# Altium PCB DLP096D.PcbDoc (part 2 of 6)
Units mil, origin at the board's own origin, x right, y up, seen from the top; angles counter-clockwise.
Board outline 4950 x 3159.45 mil, 8 copper layers (Top Layer, GND1, SIGNAL1, POWER1, POWER2, SIGNAL2, GND2, Bottom Layer), stack 60.4 mil thick; 328 components, 223 nets, 1380 pads, 856 vias.
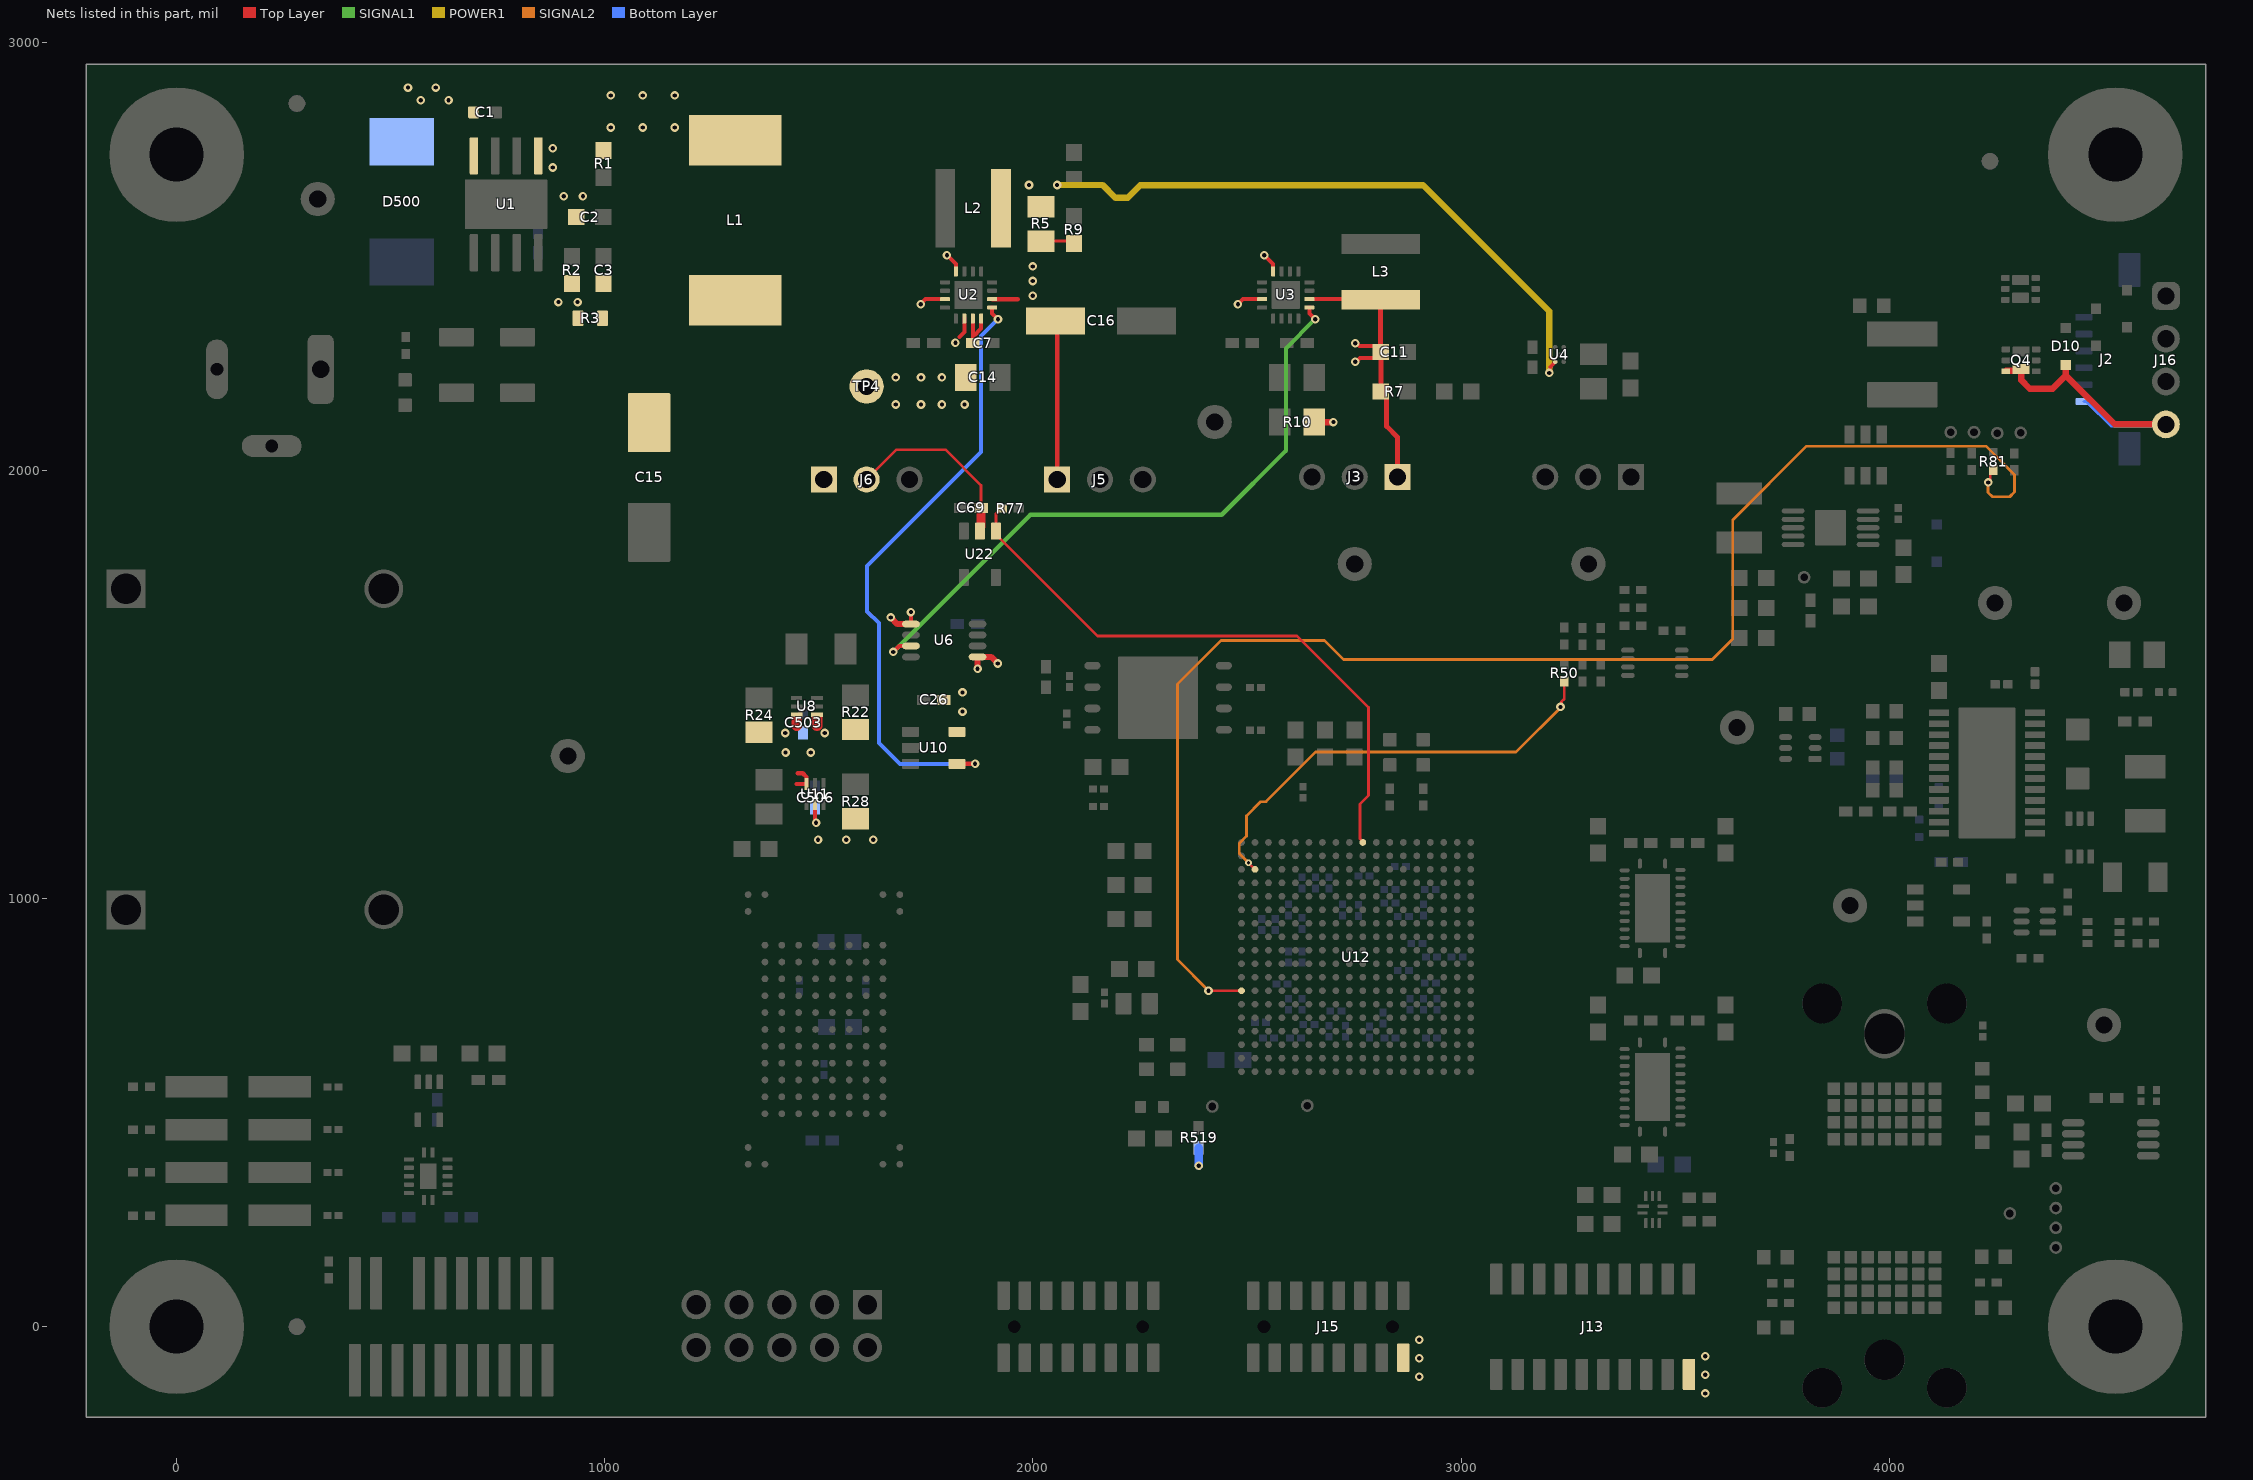
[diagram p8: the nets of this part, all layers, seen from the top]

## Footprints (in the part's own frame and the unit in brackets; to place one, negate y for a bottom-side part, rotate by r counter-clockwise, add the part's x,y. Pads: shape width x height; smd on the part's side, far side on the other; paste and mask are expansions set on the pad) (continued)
PWP0024B_NV_L [mm] "TSOP, 24-Leads, Body 7.9x4.5mm (max), Pitch 0.65mm, IPC High Density"
  rrect25% 1.2x0.4 smd: 1(-2.85,3.575) 2(-2.85,2.925) 3(-2.85,2.275) 4(-2.85,1.625) 5(-2.85,0.975) 6(-2.85,0.325) 7(-2.85,-0.325) 8(-2.85,-0.975) 9(-2.85,-1.625) 10(-2.85,-2.275) 11(-2.85,-2.925) 12(-2.85,-3.575) 13(2.85,-3.575) 14(2.85,-2.925) 15(2.85,-2.275) 16(2.85,-1.625) 17(2.85,-0.975) 18(2.85,-0.325) 19(2.85,0.325) 20(2.85,0.975) 21(2.85,1.625) 22(2.85,2.275) 23(2.85,2.925) 24(2.85,3.575)
  rrect6% 3.4x7.8 smd paste-2 mask-2: 25(0,0)
  rrect4% 2.4x5.16 on Top Paste: 25(0,0)
  rrect4% 2.4x5.16 on Top Solder: 25(0,0)
  silkscreen extent -2,-3.95 1.7,3.95, body extent -3.21,-3.9 3.21,3.9, height 1.2
RGT0016C [mm] "QFN, 16-Leads, Body 3x3mm, Pitch 0.5mm, Thermal Pad 1.7x1.7mm, TI Recommended"
  rrect42% 0.6x0.24 smd: 1(-1.4,0.75) 2(-1.4,0.25) 3(-1.4,-0.25) 4(-1.4,-0.75) 9(1.4,-0.75) 10(1.4,-0.25) 11(1.4,0.25) 12(1.4,0.75)
  rrect42% 0.24x0.6 smd: 5(-0.75,-1.4) 6(-0.25,-1.4) 7(0.25,-1.4) 8(0.75,-1.4) 13(0.75,1.4) 14(0.25,1.4) 15(-0.25,1.4) 16(-0.75,1.4)
  rrect6% 1.55x1.55 on Top Paste: 17(0,0)
  rrect6% 1.68x1.68 smd paste-0.85: 17(0,0)
  silkscreen extent -1.72,-1.73 1.73,1.73, body extent -1.5,-1.5 1.5,1.5, height 1
RHL0024A [mm]
  oval 0.24x0.6 smd: 1(-0.75,2.65) 12(-0.75,-2.65) 13(0.75,-2.65) 24(0.75,2.65)
  oval 0.6x0.24 smd: 2(-1.65,2.25) 3(-1.65,1.75) 4(-1.65,1.25) 5(-1.65,0.75) 6(-1.65,0.25) 7(-1.65,-0.25) 8(-1.65,-0.75) 9(-1.65,-1.25) 10(-1.65,-1.75) 11(-1.65,-2.25) 14(1.65,-2.225) 15(1.65,-1.725) 16(1.65,-1.225) 17(1.65,-0.725) 18(1.65,-0.225) 19(1.65,0.275) 20(1.65,0.775) 21(1.65,1.275) 22(1.65,1.775) 23(1.65,2.275)
  rect 2.05x4.05 smd paste-1.1: 25(0,0)
  Top Layer region: 0.396,-2 0.154,-2 0.154,-2.75 0.396,-2.75
  Top Layer region: -0.152,-2 -0.394,-2 -0.394,-2.75 -0.152,-2.75
  Top Layer region: -0.395,2.024 0.395,2.024 0.395,2.225 -0.395,2.225
  Top Layer region: 0.152,2 0.394,2 0.394,2.75 0.152,2.75
  Top Layer region: -0.396,2 -0.154,2 -0.154,2.75 -0.396,2.75
  Top Layer region: -0.395,-2.225 0.395,-2.225 0.395,-2.024 -0.395,-2.024
  silkscreen extent -1.95,-2.95 1.95,2.95, body extent -1.82,-2.82 1.82,2.82, height 1.01
RSW0010A [mm] "QFN, 10-Leads, Body 1.8x1.4 mm, Pitch 0.4mm, TI Recommended"
  rrect50% 0.7x0.2 smd: 1(-0.55,0.2)
  rrect50% 0.6x0.2 smd: 2(-0.6,-0.2) 6(0.6,-0.2) 7(0.6,0.2)
  rrect50% 0.2x0.6 smd: 3(-0.4,-0.8) 4(0,-0.8) 5(0.4,-0.8) 8(0.4,0.8) 9(0,0.8) 10(-0.4,0.8)
  silkscreen extent -0.88,-1.08 0.88,1.08, body extent -0.7,-0.9 0.7,0.9, height 0.56
Samtec_FLE-108-01-x-DV-A [mm] "Receptacle, 1.27mm, 8x2, SMT"
  rrect14% 0.74x1.675 smd: 1(-4.445,1.843) 2(-4.445,-1.842) 3(-3.175,1.843) 4(-3.175,-1.842) 5(-1.905,1.843) 6(-1.905,-1.842) 7(-0.635,1.843) 8(-0.635,-1.842) 9(0.635,1.843) 10(0.635,-1.842) 11(1.905,1.843) 12(1.905,-1.842) 13(3.175,1.843) 14(3.175,-1.842) 15(4.445,1.843) 16(4.445,-1.842)
  round 0.46 hole 0.76 unplated: ""(-3.81,0) ""(3.81,0)
  silkscreen extent -5.5,-1.5 5.2,1.5, body extent -5.14,-2.3 5.14,2.3, height 4.55
Samtec_RSM-110-02-x-D [mm] "Receptacle, 1.27mm, 10x2, SMT"
  rrect14% 0.74x1.84 smd: 1(-5.715,2.825) 2(-5.715,-2.825) 3(-4.445,2.825) 4(-4.445,-2.825) 5(-3.175,2.825) 6(-3.175,-2.825) 7(-1.905,2.825) 8(-1.905,-2.825) 9(-0.635,2.825) 10(-0.635,-2.825) 11(0.635,2.825) 12(0.635,-2.825) 13(1.905,2.825) 14(1.905,-2.825) 15(3.175,2.825) 16(3.175,-2.825) 17(4.445,2.825) 18(4.445,-2.825) 19(5.715,2.825) 20(5.715,-2.825)
  body extent -6.48,-3.24 6.48,3.24, height 6.1
Samtec_TSM-104-01-x-DV [mm] "Header, 2.54mm, 4x2, SMT"
  rect 3.68x1.27 smd: 1(-2.475,3.81) 2(2.475,3.81) 3(-2.475,1.27) 4(2.475,1.27) 5(-2.475,-1.27) 6(2.475,-1.27) 7(-2.475,-3.81) 8(2.475,-3.81)
  silkscreen extent -1.65,-5.08 1.65,5.22, body extent -3.85,-5.08 3.85,5.08, height 9.65
SM_RADIAL_6.3BMM [mm] "Nichicon 6.3x7.7"
  rect 3.5x1.6 smd: 1(-2.7,0) 2(2.7,0)
  silkscreen extent -3.4,-3.4 3.4,3.4, body extent -3.4,-3.4 3.4,3.4, height 8
SMC [mil] "Molded Diode, 2-Leads, Body 6.9x5.8mm, IPC Medium Density, based on OnSemi component dimensions and land patterns"
  rect 110x150 smd: 1(-140.49,0) 2(140.49,0)
  silkscreen extent -221,-123 189,124, body extent -156,-116 156,116, height 91
SOD-323#1 [mm] "NXP recommended land pattern"
  rect 0.6x0.6 smd paste-0.05: 1(-1.1,0) 2(1.1,0)
  silkscreen extent -2.06,-0.86 1.53,0.86, body extent -1.3,-0.67 1.3,0.68, height 1.1
SOD-323#2 [mm] "NXP recommended land pattern"
  rect 0.6x0.6 smd: 1(-1.1,0) 2(1.1,0)
  silkscreen extent -2.06,-0.86 1.53,0.86, body extent -1.3,-0.67 1.3,0.68, height 1.1
SOT-26 [mm] "SOT23, 6-Leads, Body 3.1x3.0mm (max), Pitch 0.95mm, IPC Medium Density based on Diodes Inc ap02002.pdf rev 29"
  rect 1.05x0.6 smd: 1(-1.225,0.95) 2(-1.225,0) 3(-1.225,-0.95) 4(1.225,-0.95) 5(1.225,0) 6(1.225,0.95)
  silkscreen extent -0.3,-1.55 0.3,1.55, body extent -1.5,-1.5 1.5,1.5, height 1.3
SOT-363 [mm]
  rect 0.6x0.42 smd: 1(-0.95,0.65) 2(-0.95,0) 3(-0.95,-0.65) 4(0.95,-0.65) 5(0.95,0) 6(0.95,0.65)
  silkscreen extent -0.38,-1.02 0.38,1.02, body extent -1.1,-1.1 1.1,1.1, height 1.12
SRN5040TA [mm] "Bourns"
  rrect7% 1.5x4.2 smd: 1(-1.8,0) 2(1.8,0)
  body extent -2.42,-2.43 2.43,2.42, height 3.81
TI_Stacked_Overlay_Small [mil]
  silkscreen extent -418,-98 418,98
TP_H045P075 [mm] "TP_H0.45P0.75"
  round 0.75 hole 0.45: 1(0,0)
TSW-104-07-G-S [mm] "Samtec 100mil, 1x4, 230 mil above insulator"
  rrect50% 1.65x1.65 hole 1.016: 1(-3.81,0)
  round 1.65 hole 1.016: 2(-1.27,0) 3(1.27,0) 4(3.81,0)
  body extent -5.08,-1.27 5.08,1.27, height 8.38
U-DFN2020-6_B [mm] "SMD, 6-Leads, Body 2x2mm, Pitch 0.65mm"
  rrect29% 0.5x0.35 smd: 1(-0.9,0.65) 2(-0.9,0) 3(-0.9,-0.65) 4(0.9,-0.65) 5(0.9,0) 6(0.9,0.65)
  rrect17% 1x0.6 smd: 7(0,0.525) 8(0,-0.525)
  silkscreen extent -1.04,-1.19 1.04,1.4, body extent -1.04,-1.04 1.04,1.04, height 0.58
WEEE_Minimum [mil] "WEEElie bin"
  silkscreen extent -95,-172 99,104
XAL5030 [mil] "Coilcraft XAL5030 12/12/11"
  rect 46x183 smd: 1(-65,0) 2(65,0)
  silkscreen extent -108,-112 108,112, body extent -108,-112 108,112, height 122
YZR0005AEBA [mm] "Micro SMD, 5-Leads, Body 1.39x1.06mm, Pitch 0.5mm, NSC Recommended"
  round 0.265 smd paste-0.132 mask+0.05: A1(-0.25,0.433) A3(0.25,0.433) B2(0,0) C1(-0.25,-0.433) C3(0.25,-0.433)
  silkscreen extent -0.68,0.75 -0.58,0.85, body extent -0.53,-0.7 0.53,0.69, height 0.68
ZCZ0324A-MFG [mm]
  round 0.4 smd paste+0 mask+0: A1(-6.8,6.8) A2(-6,6.8) A3(-5.2,6.8) A4(-4.4,6.8) A5(-3.6,6.8) A6(-2.8,6.8) A7(-2,6.8) A8(-1.2,6.8) A9(-0.4,6.8) A10(0.4,6.8) A11(1.2,6.8) A12(2,6.8) A13(2.8,6.8) A14(3.6,6.8) A15(4.4,6.8) A16(5.2,6.8) A17(6,6.8) A18(6.8,6.8) B1(-6.8,6) B2(-6,6) B3(-5.2,6) B4(-4.4,6) B5(-3.6,6) B6(-2.8,6) B7(-2,6) B8(-1.2,6) B9(-0.4,6) B10(0.4,6) B11(1.2,6) B12(2,6) B13(2.8,6) B14(3.6,6) B15(4.4,6) B16(5.2,6) B17(6,6) B18(6.8,6) C1(-6.8,5.2) C2(-6,5.2) C3(-5.2,5.2) C4(-4.4,5.2) C5(-3.6,5.2) C6(-2.8,5.2) C7(-2,5.2) C8(-1.2,5.2) C9(-0.4,5.2) C10(0.4,5.2) C11(1.2,5.2) C12(2,5.2) C13(2.8,5.2) C14(3.6,5.2) C15(4.4,5.2) C16(5.2,5.2) C17(6,5.2) C18(6.8,5.2) D1(-6.8,4.4) D2(-6,4.4) D3(-5.2,4.4) D4(-4.4,4.4) D5(-3.6,4.4) D6(-2.8,4.4) D7(-2,4.4) D8(-1.2,4.4) D9(-0.4,4.4) D10(0.4,4.4) D11(1.2,4.4) D12(2,4.4) D13(2.8,4.4) D14(3.6,4.4) D15(4.4,4.4) D16(5.2,4.4) D17(6,4.4) D18(6.8,4.4) E1(-6.8,3.6) E2(-6,3.6) E3(-5.2,3.6) E4(-4.4,3.6) E5(-3.6,3.6) E6(-2.8,3.6) E7(-2,3.6) E8(-1.2,3.6) E9(-0.4,3.6) E10(0.4,3.6) E11(1.2,3.6) E12(2,3.6) E13(2.8,3.6) E14(3.6,3.6) E15(4.4,3.6) E16(5.2,3.6) E17(6,3.6) E18(6.8,3.6) F1(-6.8,2.8) F2(-6,2.8) F3(-5.2,2.8) F4(-4.4,2.8) F5(-3.6,2.8) F6(-2.8,2.8) F7(-2,2.8) F8(-1.2,2.8) F9(-0.4,2.8) F10(0.4,2.8) F11(1.2,2.8) F12(2,2.8) F13(2.8,2.8) F14(3.6,2.8) F15(4.4,2.8) F16(5.2,2.8) F17(6,2.8) F18(6.8,2.8) G1(-6.8,2) G2(-6,2) G3(-5.2,2) G4(-4.4,2) G5(-3.6,2) G6(-2.8,2) G7(-2,2) G8(-1.2,2) G9(-0.4,2) G10(0.4,2) G11(1.2,2) G12(2,2) G13(2.8,2) G14(3.6,2) G15(4.4,2) G16(5.2,2) G17(6,2) G18(6.8,2) H1(-6.8,1.2) H2(-6,1.2) H3(-5.2,1.2) H4(-4.4,1.2) H5(-3.6,1.2) H6(-2.8,1.2) H7(-2,1.2) H8(-1.2,1.2) H9(-0.4,1.2) H10(0.4,1.2) H11(1.2,1.2) H12(2,1.2) H13(2.8,1.2) H14(3.6,1.2) H15(4.4,1.2) H16(5.2,1.2) H17(6,1.2) H18(6.8,1.2) J1(-6.8,0.4) J2(-6,0.4) J3(-5.2,0.4) J4(-4.4,0.4) J5(-3.6,0.4) J6(-2.8,0.4) J7(-2,0.4) J8(-1.2,0.4) J9(-0.4,0.4) J10(0.4,0.4) J11(1.2,0.4) J12(2,0.4) J13(2.8,0.4) J14(3.6,0.4) J15(4.4,0.4) J16(5.2,0.4) J17(6,0.4) J18(6.8,0.4) K1(-6.8,-0.4) K2(-6,-0.4) K3(-5.2,-0.4) K4(-4.4,-0.4) K5(-3.6,-0.4) K6(-2.8,-0.4) K7(-2,-0.4) K8(-1.2,-0.4) K9(-0.4,-0.4) K10(0.4,-0.4) K11(1.2,-0.4) K12(2,-0.4) K13(2.8,-0.4) K14(3.6,-0.4) K15(4.4,-0.4) K16(5.2,-0.4) K17(6,-0.4) K18(6.8,-0.4) L1(-6.8,-1.2) L2(-6,-1.2) L3(-5.2,-1.2) L4(-4.4,-1.2) L5(-3.6,-1.2) L6(-2.8,-1.2) L7(-2,-1.2) L8(-1.2,-1.2) L9(-0.4,-1.2) L10(0.4,-1.2) L11(1.2,-1.2) L12(2,-1.2) L13(2.8,-1.2) L14(3.6,-1.2) L15(4.4,-1.2) L16(5.2,-1.2) L17(6,-1.2) L18(6.8,-1.2) M1(-6.8,-2) M2(-6,-2) M3(-5.2,-2) M4(-4.4,-2) M5(-3.6,-2) M6(-2.8,-2) M7(-2,-2) M8(-1.2,-2) M9(-0.4,-2) M10(0.4,-2) M11(1.2,-2) M12(2,-2) M13(2.8,-2) M14(3.6,-2) M15(4.4,-2) M16(5.2,-2) M17(6,-2) M18(6.8,-2) N1(-6.8,-2.8) N2(-6,-2.8) N3(-5.2,-2.8) N4(-4.4,-2.8) N5(-3.6,-2.8) N6(-2.8,-2.8) N7(-2,-2.8) N8(-1.2,-2.8) N9(-0.4,-2.8) N10(0.4,-2.8) N11(1.2,-2.8) N12(2,-2.8) N13(2.8,-2.8) N14(3.6,-2.8) N15(4.4,-2.8) N16(5.2,-2.8) N17(6,-2.8) N18(6.8,-2.8) P1(-6.8,-3.6) P2(-6,-3.6) P3(-5.2,-3.6) P4(-4.4,-3.6) P5(-3.6,-3.6) P6(-2.8,-3.6) P7(-2,-3.6) P8(-1.2,-3.6) P9(-0.4,-3.6) P10(0.4,-3.6) P11(1.2,-3.6) P12(2,-3.6) P13(2.8,-3.6) P14(3.6,-3.6) P15(4.4,-3.6) P16(5.2,-3.6) P17(6,-3.6) P18(6.8,-3.6) R1(-6.8,-4.4) R2(-6,-4.4) R3(-5.2,-4.4) R4(-4.4,-4.4) R5(-3.6,-4.4) R6(-2.8,-4.4) R7(-2,-4.4) R8(-1.2,-4.4) R9(-0.4,-4.4) R10(0.4,-4.4) R11(1.2,-4.4) R12(2,-4.4) R13(2.8,-4.4) R14(3.6,-4.4) R15(4.4,-4.4) R16(5.2,-4.4) R17(6,-4.4) R18(6.8,-4.4) T1(-6.8,-5.2) T2(-6,-5.2) T3(-5.2,-5.2) T4(-4.4,-5.2) T5(-3.6,-5.2) T6(-2.8,-5.2) T7(-2,-5.2) T8(-1.2,-5.2) T9(-0.4,-5.2) T10(0.4,-5.2) T11(1.2,-5.2) T12(2,-5.2) T13(2.8,-5.2) T14(3.6,-5.2) T15(4.4,-5.2) T16(5.2,-5.2) T17(6,-5.2) T18(6.8,-5.2) U1(-6.8,-6) U2(-6,-6) U3(-5.2,-6) U4(-4.4,-6) U5(-3.6,-6) U6(-2.8,-6) U7(-2,-6) U8(-1.2,-6) U9(-0.4,-6) U10(0.4,-6) U11(1.2,-6) U12(2,-6) U13(2.8,-6) U14(3.6,-6) U15(4.4,-6) U16(5.2,-6) U17(6,-6) U18(6.8,-6) V1(-6.8,-6.8) V2(-6,-6.8) V3(-5.2,-6.8) V4(-4.4,-6.8) V5(-3.6,-6.8) V6(-2.8,-6.8) V7(-2,-6.8) V8(-1.2,-6.8) V9(-0.4,-6.8) V10(0.4,-6.8) V11(1.2,-6.8) V12(2,-6.8) V13(2.8,-6.8) V14(3.6,-6.8) V15(4.4,-6.8) V16(5.2,-6.8) V17(6,-6.8) V18(6.8,-6.8)
  silkscreen extent -8.15,-7.55 7.55,7.55, body extent -8.05,-8.05 8.05,8.05, height 0.25

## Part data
C1: library part CMP-0086535-1, "0.1µF ±10% 50V Ceramic Capacitor X8L 0603 (1608 Metric)", Manufacturer="Murata Electronics North America", TempCo=-40+15%, Tolerance_%=10%
C2: library part CMP-0006792-3, "CAP, CERM, 56 pF, 50 V, +/- 1%, C0G/NP0, 0603", Cap_Case=0603, Manufacturer=AVX, Supplier Part Number 1=478-7922-1-ND, TempCo=C0G/NP0, Tolerance_%=1%, Value1=Unknown, Value2=50V, ValueDisplayed=56pF
C3: library part CMP-0007180-1, "CAP, CERM, 1200 pF, 50 V, +/- 5%, C0G/NP0, 0603", Cap_Case=0603, Manufacturer=MuRata, Supplier Part Number 1=490-1453-1-ND, TempCo=C0G/NP0, Tolerance_%=5%, Value1=Unknown, Value2=50V, ValueDisplayed=1200pF
C4 C5: library part CMP-0089367-1, "2.2µF ±10% 100V Ceramic Capacitor X8L 1210 (3225 Metric)", Digikey Part Number=490-GCJ32DL8EL225KA07LCT-ND, Manufacturer=Murata, Mouser Part Number=81-GCJ32DL8EL225KA7L, Operating Temperature Range="-55°C to +150°C", TempCo=+15/-40%, Temperature Characteristic=X8L, Tolerance_%=10%, ValueDisplayed=2.2uF
C6: library part CMP-0080703-2, "CAP, CERM, 390 pF, 50 V,+/- 10%, X7R, AEC-Q200 Grade 1, 0402", Cap_Case=0402, Manufacturer=MuRata, Supplier Part Number 1=81-GCM155R71H391KA7D, TempCo=X7R, Tolerance_%=10%, Value2=50V, ValueDisplayed=390pF
C7 C9 C26 C65 C69 C501 C503 C506 C507 C555 C556 C557: library part CMP-0078241-1, "CAP, CERM, 0.1 µF, 10 V,+/- 10%, X7R, 0402", Cap_Case=0402, Manufacturer=Kemet, Supplier Part Number 1=399-3520-1-ND, TempCo=X7R, Tolerance_%=10%, Value2=10V, ValueDisplayed=0.1µF
C8: library part CMP-0006310-2, "CAP, CERM, 150 pF, 50 V, +/- 5%, C0G/NP0, AEC-Q200 Grade 1, 0402", Cap_Case=0402, Manufacturer=TDK, Supplier Part Number 1=445-5598-1-ND, TempCo=C0G/NP0, Tolerance_%=5%, Value1=Unknown, Value2=50V, ValueDisplayed=150pF
C10: library part CMP-0080385-1, "CAP, CERM, 4.7 µF,  VAC/6.3 VDC,+/- 20%, X5R, 0402", Cap_Case=0402, Manufacturer=MuRata, Supplier Part Number 1=GRM155R60J475ME47J-ND, TempCo=X5R, Tolerance_%=20%, Value1="0.001 ohm", Value2=6.3V, ValueDisplayed=4.7µF
C11 C12 C51: library part CMP-0078295-1, "CAP, CERM, 22 µF, 6.3 V,+/- 20%, X5R, 0603", Cap_Case=0603, Manufacturer=MuRata, Supplier Part Number 1=490-13241-1-ND, TempCo=X5R, Tolerance_%=20%, Value2=6.3V, ValueDisplayed=22µF
C13 C14: library part CMP-0085574-1, "CAP, CERM, 10 µF, 10 V,+80/-20%, Y5V, 0805", Cap_Case=0805, Manufacturer=Yageo, TempCo=Y5V, Tolerance_%=80%, Value2=10V, ValueDisplayed=10µF
C15: library part CMP-0081924-1, "CAP, AL, 330 µF, 10 V, +/- 20%, SMD", Cap_Case=8x10mm, Manufacturer=Nichicon, Supplier Part Number 1=493-3905-1-ND, Tolerance_%=20%, Value2=10V, ValueDisplayed=330µF
C16: library part CMP-0011112-1, "CAP, AL, 220 uF, 10 V, +/- 20%, 0.34 ohm, SMD", Cap_Case=6.3x7.7, Manufacturer=Nichicon, Supplier Part Number 1=493-2250-1-ND, Tolerance_%=20%, Value1="0.34 ohm", Value2=10V, ValueDisplayed=220uF
C17 C35 C36 C48 C508 C509 C510 C511 C512 C514 C515 C516 C517 C518 C519 C520 C522 C523 C524 C525 C527 C528 C529 C530 C531 C532 C533 C534 C535 C536 C537 C538 C539 C540 C541 C542 C543 C545 C546 C547 C548 C549 C550 C551 C552 C553: library part CMP-0086059-1, "CAP, CERM, 0.1 µF, 10 V,+/- 10%, X5R, 0201", Cap_Case=0201, Manufacturer=MuRata, TempCo=X5R, Tolerance_%=10%, Value2=10V, ValueDisplayed=0.1µF
C18 C526: library part CMP-0079607-1, "CAP, CERM, 1 µF, 16 V,+/- 10%, X7R, AEC-Q200 Grade 1, 0603", Cap_Case=0603, Manufacturer=TDK, Supplier Part Number 1=445-12539-1-ND, TempCo=X7R, Tolerance_%=10%, Value2=16V, ValueDisplayed=1µF
C19 C22 C23 C38 C54 C544: library part CMP-0007022-5, "CAP, CERM, 4.7 uF, 35 V, +/- 10%, X5R, 0603", Cap_Case=0603, Manufacturer=TDK, Supplier Part Number 1=445-9064-1-ND, TempCo=X5R, Tolerance_%=10%, Value1="0.003728 ohm", Value2=35V, ValueDisplayed=4.7uF
C20 C66 C68: library part CMP-0006350-2, "CAP, CERM, 0.47 uF, 10 V, +/- 10%, X7R, AEC-Q200 Grade 1, 0402", Cap_Case=0402, Manufacturer=MuRata, Supplier Part Number 1=490-GRT155R71A474KE01DCT-ND, TempCo=X7R, Tolerance_%=10%, Value1=Unknown, Value2=10V, ValueDisplayed=0.47uF
C21: library part CMP-0006995-4, "CAP, CERM, 470 pF, 100 V, +/- 5%, C0G/NP0, 0603", Cap_Case=0603, Manufacturer=TDK, Supplier Part Number 1=445-2310-1-ND, TempCo=C0G/NP0, Tolerance_%=5%, Value1="0.0714 ohm", Value2=100V, ValueDisplayed=470pF
C24: library part CMP-0007842-2, "CAP, CERM, 10 uF, 35 V, +/- 10%, X5R, 0805", Cap_Case=0805, Manufacturer=TDK, Supplier Part Number 1=445-14417-1-ND, TempCo=X5R, Tolerance_%=10%, Value1="0.002818 ohm", Value2=35V, ValueDisplayed=10uF
C25: library part CMP-0007356-5, "CAP, CERM, 2.2 uF, 35 V, +/- 10%, X5R, 0603", Cap_Case=0603, Manufacturer=MuRata, Supplier Part Number 1=490-7204-6-ND, TempCo=X5R, Tolerance_%=10%, Value1=Unknown, Value2=35V, ValueDisplayed=2.2uF
C27 C28 C33 C59 C63 C64 C70: library part CMP-0007094-5, "CAP, CERM, 0.22 uF, 50 V, +/- 10%, X7R, AEC-Q200 Grade 1, 0603", Cap_Case=0603, Manufacturer=TDK, PartNumber=CGA3E3X7R1H224K080AB, Supplier Part Number 1=445-6926-1-ND, TempCo=X7R, Tolerance_%=10%, Value1="0.021699 ohm", Value2=50V, ValueDisplayed=0.22uF
C29: library part CMP-0006682-2, "CAP, CERM, 220 pF, 50 V, +/- 10%, X7R, 0402", Cap_Case=0402, Manufacturer=MuRata, Supplier Part Number 1=490-1298-1-ND, TempCo=X7R, Tolerance_%=10%, Value1=Unknown, Value2=50V, ValueDisplayed=220pF
C30 C31 C32 C43 C44 C45 C46 C47 C513 C521 C554: library part CMP-0007008-1, "CAP, CERM, 3.3 uF, 25 V, +/- 10%, X5R, 0603", Cap_Case=0603, Manufacturer=TDK, Supplier Part Number 1=445-14141-1-ND, TempCo=X5R, Tolerance_%=10%, Value1=Unknown, Value2=25V, ValueDisplayed=3.3uF
C34 C37 C504: library part CMP-0007139-4, "CAP, CERM, 1 uF, 25 V, +/- 10%, X7R, AEC-Q200 Grade 1, 0603", Cap_Case=0603, Manufacturer=MuRata, Supplier Part Number 1=490-10673-1-ND, TempCo=X7R, Tolerance_%=10%, Value1=Unknown, Value2=25V, ValueDisplayed=1uF
C39: library part CMP-0088003-2, "CAP CER 22UF 10V X7S 1206", Manufacturer=TDK, TempCo=30ppm/°C, Tolerance_%=20%, ValueDisplayed=22µF
C40: library part CMP-0006323-2, "CAP, CERM, 6800 pF, 50 V, +/- 10%, X7R, AEC-Q200 Grade 1, 0402", Cap_Case=0402, Manufacturer=TDK, Supplier Part Number 1=445-6892-1-ND, TempCo=X7R, Tolerance_%=10%, Value1="0.391597 ohm", Value2=50V, ValueDisplayed=6800pF
C41 C42 C49 C50 C56 C57 C71: library part CMP-0861000-1, "CAP, CERM, 0.1 µF, 25 V,+/- 10%, X8L, AEC-Q200 Grade 0, 0402", Cap_Case=0402, Manufacturer=MuRata, TempCo=X8L, Tolerance_%=10%, Value2=25V, ValueDisplayed=0.1µF
C52 C53 C58: library part CMP-0084284-1, "CAP, CERM, 2.2 µF, 10 V,+/- 10%, X7R, AEC-Q200 Grade 1, 0603", Cap_Case=0603, Manufacturer=MuRata, TempCo=X7R, Tolerance_%=10%, Value2=10V, ValueDisplayed=2.2µF
C55 C60 C61 C62: library part CMP-0006350-2, "CAP, CERM, 0.1 uF, 10 V, +/- 10%, X7R, AEC-Q200 Grade 1, 0402", Cap_Case=0402, Manufacturer=MuRata, Supplier Part Number 1=81-GCM155R71A104K5D, TempCo=X7R, Tolerance_%=10%, Value1=Unknown, Value2=10V, ValueDisplayed=0.1uF
C72: library part CMP-0006416-2, "CAP, CERM, 120 pF, 50 V, +/- 1%, C0G/NP0, 0402", Cap_Case=0402, Manufacturer=MuRata, Supplier Part Number 1=490-8182-1-ND, TempCo=C0G/NP0, Tolerance_%=1%, Value1=Unknown, Value2=50V, ValueDisplayed=120pF
C505: library part CMP-0007094-5, "CAP, CERM, 0.22 uF, 50 V, +/- 10%, X7R, AEC-Q200 Grade 1, 0603", Cap_Case=0603, Manufacturer=TDK, Supplier Part Number 1=445-6926-1-ND, TempCo=X7R, Tolerance_%=10%, Value1="0.021699 ohm", Value2=50V, ValueDisplayed=0.22uF
D1 D9 D10 D501: library part CMP-0079598-2, "Diode, Schottky, 30 V, 0.5 A, AEC-Q101, SOD-323", Manufacturer="Diodes Inc.", Value1=0.5A, Value2=0.4V
D2 D5 D6: library part CMP-0092845-1, "LED Uni-Color Red 643nm 2-Pin Chip 0603(1608Metric) T/R", Color=Red, Digikey Part Number=475-3124-1-ND, Forward Current=2mA, Manufacturer="OSRAM Opto Semiconductors", Mouser Part Number=720-LSL29K-G1H2-1-Z, Operating Temperature Range="-40°C to +100°C"
D3: library part CMP-0028830-2, "Diode, Schottky, 40 V, 2 A, AEC-Q101, SOT-26", Manufacturer="Diodes Inc.", Value1=2A, Value2=0.5V
D4: library part CMP-0028814-3, "Diode, Schottky, 20 V, 1.1 A, AEC-Q101, DO-219AB", Manufacturer=Vishay-Semiconductor, Value1=1.1A, Value2=0.42V
D7: library part CMP-0086617-1, "Diode Array 2 Pair Series Connection Schottky 30V 200mA (DC) Surface Mount 6-TSSOP, SC-88, SOT-363", Manufacturer=Nexperia
D8: library part CMP-0085730-1, "Diode, Zener, 3.3 V, 300 mW, AEC-Q101, SOD-323", Manufacturer="ON Semiconductor", Power_W=300mW, Value1=0.3W
D500: library part CMP-0077948-2, "Diode, Schottky, 40 V, 5 A, AEC-Q101, SMC", Manufacturer="Diodes Inc.", Value1=5A, Value2=0.55V
FB2: library part CMP-0089199-1, "120 Ohms @ 100MHz 1  Ferrite Bead 0603 (1608 Metric) 2A 40mOhm", Digikey Part Number=490-3991-1-ND, Impedance At Frequency="120Ω @ 100MHz", Manufacturer=Murata, Mouser Part Number=81-BLM18EG121SN1D, Operating Temperature Range="-55°C to +125°C", Tolerance_%=25%
FID1 FID2 FID3 FID4 FID5 FID6: library part CMP-0077181-1, "Fiducial mark.  There is nothing to buy or mount.", Manufacturer=N/A
H1 H2 H3 H4: library part CMP-0003617-1, "Machine Screw, Round, #4-40 x 1/4, Nylon, Philips panhead", Manufacturer="B&F Fastener Supply", Supplier Part Number 1=H542-ND
H500 H501 H502 H503: library part CMP-0003610-1, "Standoff, Hex, 0.5\"L #4-40 Nylon", Manufacturer=Keystone, Supplier Part Number 1=36-1902C-ND
J1: library part CMP-0055800-1, "Power Jack, 2.1x5.5mm, R/A, TH", Color=Black, Current_A=5A, Manufacturer="Memory Protection Devices", Supplier Part Number 1=EJ508A-ND, Voltage_V=12V
J2: library part CMP-0090189-1, "6 Position FFC, FPC Connector Contacts, Bottom 0.039\" (1.00mm) Surface Mount, Right Angle from Molex", Current_A=1A, Digikey Part Number=WM24188CT-ND, Manufacturer=Molex, Mouser Part Number=538-200528-0060, Operating Temperature Range="-40°C to +105°C", Voltage_V=125V
J3 J4 J5 J6: library part CMP-0055332-1, "Header, 2.54mm, 3x1, Tin, TH", Color=Black, Current_A=4A, Manufacturer=Molex, Supplier Part Number 1=WM50016-03-ND, Voltage_V=250V
J7: library part CMP-0055393-3, "Standard Banana Jack, insulated, 10A, red", Manufacturer="DEM Manufacturing", Supplier Part Number 1=30M0087
J8: library part CMP-0055389-3, "Standard Banana Jack, insulated, 10A, black", Manufacturer="DEM Manufacturing", Supplier Part Number 1=45M6896
J9: library part CMP-0087816-2, "NTERPOSER, 56 CONTACT, HOLE DATUM", Alternate Manufacturer=Neoconix, Alternate PartNumber=BDX0056DMMSXAU00, Manufacturer="Foxconn Interconnect Technology", PartNumber=PL00561-11ZZ0-4H
J10: library part CMP-0075593-2, "Header, 2.54mm, 4x2, Gold, SMT", Color=Black, Current_A=4.9A, Manufacturer=Samtec, Supplier Part Number 1=TSM-104-01-L-DV-ND, Voltage_V=475V
J11: library part CMP-0089821-1, "Connector Header Through Hole 10 position 0.100\" (2.54mm)", Current_A=2.5A, Digikey Part Number=WM9220-ND, Manufacturer=Molex, Mouser Part Number=538-70246-1002, Operating Temperature Range="-55°C to +120°C", Voltage_V=250V
J12: library part CMP-0092119-1, "Connector Header Surface Mount 20 position 0.050\" (1.27mm)", Current_A=3.1A, Digikey Part Number=SAM8790-ND, Manufacturer=Samtec, Mouser Part Number=200-FTR11003GD06, Operating Temperature Range="-55°C to +125°C"
J13: library part CMP-0081743-1, "Receptacle, 1.27mm, 10x2, Gold with Tin tail, SMT", Color=Black, Current_A=3.1A, Manufacturer=Samtec, Supplier Part Number 1=SAM9848-ND
J14 J15: library part CMP-0077240-1, "Receptacle, 1.27mm, 8x2, Gold, SMT", Color=Black, Current_A=2A, Manufacturer=Samtec, Supplier Part Number 1=SAM9406-ND
J16: library part CMP-0075409-2, "Header, 100mil, 4x1, Gold, TH", Color=Black, Current_A=6.3A, Manufacturer=Samtec, Supplier Part Number 1=SAM1029-04-ND, Voltage_V=550V
L1: library part CMP-0061454-2, "Inductor, Shielded, Ferrite, 15 uH, 8.7 A, 0.019 ohm, SMD", Manufacturer=Coilcraft, Supplier Part Number 1=994-MSS1210-153MEB, Value1="0.019 ohm", Value2=8.7A, ValueDisplayed=15uH
L2 L3: library part CMP-0061001-2, "Inductor, Shielded, Composite, 2.2 µH, 9.2 A, 0.01 ohm, AEC-Q200 Grade 1, SMD", Manufacturer=Coilcraft, Value1="0.01 ohm", Value2=9.2A, ValueDisplayed=2.2uH
L4: library part CMP-0085685-1, "Inductor, Semi-Shielded, Ferrite, 22 µH, 1.5 A, 0.1476 ohm, AEC-Q200 Grade 1, SMD", Manufacturer=Bourns, Value1="0.1476 ohm", Value2=1.5A, ValueDisplayed=22µH
L5: library part CMP-0082247-1, "Inductor, Shielded, Ferrite, 2.2 µH, 0.7 A, 0.364 ohm, SMD", Manufacturer=TDK, Value1="0.364 ohm", Value2=0.7A, ValueDisplayed=2.2µH
L6: library part CMP-0058987-1, "Inductor, Shielded, 4.7 uH, 2.7 A, 0.083 ohm, AEC-Q200 Grade 1, SMD", Manufacturer="MuRata Toko", PartNumber=FDSD0420D-4R7M{}P3, Value1="0.083 ohm", Value2=2.7A, ValueDisplayed=4.7uH
LBL1: library part CMP-0003625-1, "Thermal Transfer Printable Labels, 0.650\" W x 0.200\" H - 10,000 per roll", Manufacturer=Brady, Supplier Part Number 1=97C5133
Logo1: library part CMP-0074847-1, "FCC_disclaimer"
Logo2: library part CMP-0074838-1, "Texas Instrument Corporate Signature"
Logo3: library part CMP-0074769-1
Logo4: library part CMP-0074844-1
Q1 Q4: library part CMP-0077941-1, "MOSFET, 2-CH, N-CH, 30 V, 7.7 A, AEC-Q101, U-DFN2020-6", Alternate Manufacturer=None, Manufacturer="Diodes Inc.", PartNumber=DMT3020LFDB-7, Supplier Part Number 1=DMT3020LFDB-7-ND, Value1="0.032 ohm", Value2="? nC"
Q2: library part CMP-0088579-4, "MOSFET 2N-CH 30V 0.35A 6TSSOP", Digikey Part Number=1727-1221-1-ND, Drain To Source Breakdown Voltage=30V, Input Capacitace At Vds="34pF @ 15V", Manufacturer=Nexperia, Mouser Part Number=771-NX3008NBKS,115, Operating Temperature Range="-55°C to +150°C", Power_W=445mW, Pulse Drain Current=1.4A, Typ Forward Diode Voltage=0.85V
Q3: library part CMP-0082233-2, "MOSFET, 2-CH, N/P-CH, -30 V, -0.2 A, AEC-Q101, SOT-363", Alternate Manufacturer=None, Manufacturer=Nexperia, Value1="4.1 ohm", Value2="0.55 nC"
R1: library part CMP-0022064-1, "RES, 158 k, 1%, 0.1 W, 0603", Manufacturer=Vishay-Dale, Power_W=100mW, Supplier Part Number 1=541-158KHCT-ND, TempCo="100 ppm/C", Tolerance_%=1%, Value2=0.1W, Value_Code=158k
R2: library part CMP-0021990-4, "RES, 100 k, 1%, 0.1 W, AEC-Q200 Grade 0, 0603", Manufacturer=Vishay-Dale, Power_W=100mW, Supplier Part Number 1=541-100KHCT-ND, TempCo="100 ppm/C", Tolerance_%=1%, Value2=0.1W, Value_Code=100k
R3: library part CMP-0093627-1, "Thick Film Chip Resistors 0603 316kΩ 0.1W 1% 100ppm/°C", Manufacturer=Bourns, Operating Temperature Range="-55°C to +155°C", Power_W=100mW, TempCo=100ppm/°C, Tolerance_%=1%
R4 R13 R31 R32 R49 R51: library part CMP-0026858-5, "RES, 1.8 k, 5%, 0.063 W, AEC-Q200 Grade 0, 0402", Manufacturer=Vishay-Dale, Power_W=63mW, Supplier Part Number 1=541-1.8KJCT-ND, TempCo="200 ppm/C", Tolerance_%=5%, Value2=0.063W, Value_Code=1k80, ValueDisplayed=1.8k
R5 R10 R22 R28: library part CMP-0021521-3, "RES, 100 k, 1%, 0.125 W, AEC-Q200 Grade 0, 0805", Manufacturer=Panasonic, Power_W=125mW, Supplier Part Number 1=P100KCCT-ND, TempCo="100 ppm/C", Tolerance_%=1%, Value2=0.125W, Value_Code=100k
R6: library part CMP-0022844-4, "RES, 180 k, 1%, 0.1 W, 0603", Manufacturer=Yageo, Power_W=100mW, Supplier Part Number 1=311-180KHRCT-ND, TempCo="100 ppm/C", Tolerance_%=1%, Value2=0.1W, Value_Code=180k
R7: library part CMP-0023267-5, "RES, 75.0 k, 1%, 0.1 W, 0603", Manufacturer=Yageo, Power_W=100mW, Supplier Part Number 1=311-75.0KHRCT-ND, TempCo="100 ppm/C", Tolerance_%=1%, Value2=0.1W, Value_Code=75k0, ValueDisplayed=75.0k
R8: library part CMP-0022808-4, "RES, 150 k, 1%, 0.1 W, 0603", Manufacturer=Yageo, Power_W=100mW, Supplier Part Number 1=311-150KHRCT-ND, TempCo="100 ppm/C", Tolerance_%=1%, Value2=0.1W, Value_Code=150k
R9: library part CMP-0023184-4, "RES, 562 k, 1%, 0.1 W, 0603", Manufacturer=Yageo, Power_W=100mW, Supplier Part Number 1=311-562KHRCT-ND, TempCo="100 ppm/C", Tolerance_%=1%, Value2=0.1W, Value_Code=562k
R11: library part CMP-0015168-2, "RES, 0.11, 1%, 0.5 W, 1210", Manufacturer=Rohm, Power_W=500mW, Supplier Part Number 1=RHM.11SCT-ND, TempCo="200 ppm/C", Tolerance_%=1%, Value2=0.5W, Value_Code=R110, ValueDisplayed=0.11
R12: library part CMP-0023308-5, "RES, 8.20 k, 1%, 0.1 W, 0603", Manufacturer=Yageo, Power_W=100mW, Supplier Part Number 1=311-8.20KHRCT-ND, TempCo="100 ppm/C", Tolerance_%=1%, Value2=0.1W, Value_Code=8k20, ValueDisplayed=8.20k
R14 R30 R50: library part CMP-0026917-5, "RES, 3.0 k, 5%, 0.063 W, AEC-Q200 Grade 0, 0402", Manufacturer=Vishay-Dale, Power_W=63mW, Supplier Part Number 1=541-3.0KJCT-ND, TempCo="200 ppm/C", Tolerance_%=5%, Value2=0.063W, Value_Code=3k00, ValueDisplayed=3.0k
R15: library part CMP-0017552-3, "RES, 3.48 k, 1%, 0.25 W, AEC-Q200 Grade 0, 1206", Manufacturer=Panasonic, Power_W=250mW, Supplier Part Number 1=P3.48KFCT-ND, TempCo="100 ppm/C", Tolerance_%=1%, Value2=0.25W, Value_Code=3k48, ValueDisplayed=3.48k
R16 R76 R520: library part CMP-0027002-2, "RES, 0, 5%, 0.063 W, 0402", Manufacturer=Rohm, Power_W=63mW, Supplier Part Number 1=RHM0.0JCT-ND, TempCo="500 ppm/C", Tolerance_%=5%, Value2=0.063W, Value_Code=0000, ValueDisplayed=0
R17: library part CMP-0088626-1, "Res Thin Film 0402 8.2K Ohm 0.1% 0.063W(1/16W) ±25ppm/C Pad SMD Automotive T/R", Digikey Part Number=P8.2KDCCT-ND, Manufacturer="Panasonic Electronic Components", Mouser Part Number=667-ERA-2AEB822X, Operating Temperature Range="-55°C to +155°C", Power_W=63mW, TempCo=25ppm/°C, Tolerance_%=0.1%
R18 R23 R25 R26 R29 R47 R63 R65 R67 R70 R82 R85 R86 R505: library part CMP-0027019-1, "RES, 10 k, 5%, 0.05 W, 0201", Manufacturer="Yageo America", Power_W=50mW, Supplier Part Number 1=311-10KNCT-ND, TempCo="200 ppm/C", Tolerance_%=5%, Value2=0.05W, Value_Code=10k0, ValueDisplayed=10k
R19 R20 R504: library part CMP-0088648-1, "Res Thin Film 0402 100K Ohm 0.1% 1/16W ±25ppm/°C Molded SMD SMD Punched Carrier T/R", Digikey Part Number=P100KDCCT-ND, Manufacturer=Panasonic, Mouser Part Number=667-ERA-2AEB104X, Octopart Part Number=aea26725a1f47165, Operating Temperature Range="-55°C to +155°C", Power_W=63mW, TempCo=25ppm/°C, Tolerance_%=0.1%
R21: library part CMP-0088630-1, "Res Thin Film 0402 15.6K Ohm 0.1% 1/10W ±25ppm/°C Molded SMD Paper T/R", Digikey Part Number=541-2079-1-ND, Manufacturer=Vishay, Mouser Part Number=71-TNPW040215K6BEED, Operating Temperature Range="-55°C to +155°C", Power_W=100mW, TempCo=25ppm/°C, Tolerance_%=0.1%
R24: library part CMP-0021770-3, "RES, 6.65 k, 1%, 0.125 W, AEC-Q200 Grade 0, 0805", Manufacturer=Panasonic, Power_W=125mW, Supplier Part Number 1=P6.65KCCT-ND, TempCo="100 ppm/C", Tolerance_%=1%, Value2=0.125W, Value_Code=6k65, ValueDisplayed=6.65k
R27: library part CMP-0020843-1, "RES, 10.2 k, 1%, 0.125 W, 0805", Manufacturer=Vishay-Dale, Power_W=125mW, Supplier Part Number 1=541-10.2KCCT-ND, TempCo="100 ppm/C", Tolerance_%=1%, Value2=0.125W, Value_Code=10k2, ValueDisplayed=10.2k
R33: library part CMP-0026517-2, "RES, 6.81 k, 1%, 0.063 W, AEC-Q200 Grade 0, 0402", Manufacturer=Vishay-Dale, Power_W=63mW, Supplier Part Number 1=541-6.81KLCT-ND, TempCo="100 ppm/C", Tolerance_%=1%, Value2=0.063W, Value_Code=6k81, ValueDisplayed=6.81k
R34 R35 R43 R44 R45 R66 R69 R72 R532: library part CMP-0025701-1, "RES, 10 k, 5%, 0.1 W, 0603", Manufacturer=Vishay-Dale, Power_W=100mW, Supplier Part Number 1=541-10KGCT-ND, TempCo="200 ppm/C", Tolerance_%=5%, Value2=0.1W, Value_Code=10k0, ValueDisplayed=10k
R36: library part CMP-0023147-2, "RES, 4.32 k, 1%, 0.1 W, 0603", Manufacturer="Yageo America", Power_W=100mW, Supplier Part Number 1=311-4.32KHRCT-ND, TempCo="200 ppm/C", Tolerance_%=1%, Value2=0.1W, Value_Code=4k32, ValueDisplayed=4.32k
R37 R39 R48 R64 R68 R71: library part CMP-0078193-1, "RES, 1.0 k, 5%, 0.1 W, AEC-Q200 Grade 0, 0402", Manufacturer=Panasonic, Power_W=100mW, Supplier Part Number 1=P1.0KJCT-ND, TempCo="200 ppm/C", Tolerance_%=5%, Value2=0.1W, Value_Code=1k00, ValueDisplayed=1.0k
R38: library part CMP-0026839-3, "RES, 13, 5%, 0.063 W, AEC-Q200 Grade 0, 0402", Manufacturer=Vishay-Dale, Power_W=63mW, Supplier Part Number 1=541-13JCT-ND, TempCo="200 ppm/C", Tolerance_%=5%, Value2=0.063W, Value_Code=13R0, ValueDisplayed=13
R40 R77: library part CMP-0026994-4, "RES, 10 k, 5%, 0.1 W, AEC-Q200 Grade 0, 0402", Manufacturer=Panasonic, Power_W=100mW, Supplier Part Number 1=P10KJCT-ND, TempCo="200 ppm/C", Tolerance_%=5%, Value2=0.1W, Value_Code=10k0, ValueDisplayed=10k
R41 R42: library part CMP-0026916-3, "RES, 39, 5%, 0.063 W, AEC-Q200 Grade 0, 0402", Manufacturer=Vishay-Dale, Power_W=63mW, Supplier Part Number 1=541-39JCT-ND, TempCo="200 ppm/C", Tolerance_%=5%, Value2=0.063W, Value_Code=39R0, ValueDisplayed=39
R46: library part CMP-0022707-2, "RES, 49.9, 1%, 0.1 W, AEC-Q200 Grade 0, 0603", Manufacturer=Panasonic, Power_W=100mW, Supplier Part Number 1=P49.9HCT-ND, TempCo="100 ppm/C", Tolerance_%=1%, Value2=0.1W, Value_Code=49R9, ValueDisplayed=49.9
R62: library part CMP-0026240-2, "RES, 2.32 k, 1%, 0.063 W, AEC-Q200 Grade 0, 0402", Manufacturer=Vishay-Dale, Power_W=63mW, Supplier Part Number 1=541-2.32KLCT-ND, TempCo="100 ppm/C", Tolerance_%=1%, Value2=0.063W, Value_Code=2k32, ValueDisplayed=2.32k
R73 R519: library part CMP-0025958-2, "RES, 10.0 k, 1%, 0.063 W, 0402", Manufacturer=Vishay-Dale, Power_W=63mW, Supplier Part Number 1=541-10.0KLCT-ND, TempCo="100 ppm/C", Tolerance_%=1%, Value2=0.063W, Value_Code=10k0, ValueDisplayed=10.0k
R74: library part CMP-0089632-1, "0 Ohms Jumper 0.125W, 1/8W Chip Resistor 0805 (2012 Metric) Automotive AEC-Q200 Thick Film", Digikey Part Number=RMCF0805ZT0R00CT-ND, Manufacturer="Stackpole Electronics", Operating Temperature Range="-55°C to +155°C", Power_W=125mW, TempCo=200ppm/°C
R75 R78 R79 R80 R81: library part CMP-0026993-2, "RES, 100, 5%, 0.1 W, AEC-Q200 Grade 0, 0402", Manufacturer=Panasonic, Power_W=100mW, Supplier Part Number 1=P100JCT-ND, TempCo="200 ppm/C", Tolerance_%=5%, Value2=0.1W, Value_Code=100R, ValueDisplayed=100
R83 R84: library part CMP-0023188-5, "RES, 56.0, 1%, 0.1 W, 0603", Manufacturer=Yageo, Power_W=100mW, Supplier Part Number 1=311-56.0HRCT-ND, TempCo="100 ppm/C", Tolerance_%=1%, Value2=0.1W, Value_Code=56R0, ValueDisplayed=56.0
R500: library part CMP-0026371-2, "RES, 41.2 k, 1%, 0.063 W, AEC-Q200 Grade 0, 0402", Manufacturer=Vishay-Dale, Power_W=63mW, Supplier Part Number 1=541-41.2KLCT-ND, TempCo="100 ppm/C", Tolerance_%=1%, Value2=0.063W, Value_Code=41k2, ValueDisplayed=41.2k
R503: library part CMP-0088636-1, "RES SMD 12.1KOHM 0.1% 1/16W 0402", Digikey Part Number=P12.1KDCCT-ND, Manufacturer="Panasonic Electronic Components", Mouser Part Number=667-ERA-2AEB1212X, Operating Temperature Range="-55°C to +155°C", Power_W=63mW, TempCo=25ppm/°C, Tolerance_%=0.1%
SH-J1 SH-J2 SH-J3 SH-J4 SH-J5 SH-J6 SH-J7 SH-J8: library part CMP-0078738-1, "Single Operation 2.54mm Pitch Open Top Jumper Socket", Manufacturer=Harwin, Supplier Part Number 1=952-2881-ND
TP1 TP4 TP5 TP6 TP7 TP8 TP10 TP11 TP12 TP17: library part CMP-0055138-1, "Test Point, Miniature, Black, TH", Color=Black, Manufacturer=Keystone, Supplier Part Number 1=36-5001-ND
TP2 TP3 TP13 TP14 TP15 TP16 TP18 TP19 TP20 TP21 TP22: library part CMP-0003719-1, "Testpoint", Manufacturer="Texas Instruments"
TP9: library part CMP-0055138-2, "Test Point, Miniature, Black, TH", Color=Black, Manufacturer="Keystone Electronics", Supplier Part Number 1=36-5001-ND
TP23: library part CMP-0003719-1, "Testpoint", Manufacturer="Texas Instruments", PartNumber=TP_H0.45P0.75
U1: library part CMP-0091061-1, "100-V Input, 3.5-A Non-Synchronous Buck DC/DC Converter with Ultra-low IQ", Manufacturer="Texas Instruments", Max Supply Voltage=100V, Min Supply Voltage=6V, Nominal Supply Current=300uA, Operating Temperature Range="-40°C to +150°C", Output Voltage=1.2-90V, Switching Frequency=1MHz
U2 U3: library part CMP-0083641-1, "TPS62130A-Q1 3 to 17-V 3-A Automotive Step-Down Converter in 3 × 3 QFN Package, RGT0016C (VQFN-16)", Alternate Manufacturer="Texas Instruments", Alternate PartNumber=TPS62130AQRGTRQ1, Operating Temperature Range="-40 to 125 C", Rating=Automotive
U4: library part CMP-0071334-1, "2MHz, 600mA Step-Down DC-DC Converter, 5-pin Micro SMD, Pb-Free", Manufacturer="Texas Instruments", PackageTopMarking="XV*I B", PartNumber=LM3671QTLX-1.8/NOPB, PowerWise=Y
U5: library part CMP-0073710-1, "2A LED Driver with Integrated NFET, High-Side Current Sense, and Shunt PWM Dimming Capable, DGQ0010E (VSSOP-10)", Alternate Manufacturer="Texas Instruments", Alternate PartNumber=TPS92515QDGQQ1
U6: library part CMP-0051803-1, "Automotive Catalog Dual 2-Input Positive-AND Gate, DCT0008A, LARGE T&R", F @ Nom Voltage(Max)(Mhz)=150, Generic Part Number=SN74LVC2G08-Q1, ICC @ Nom Voltage(Max)(mA)=0.01, Manufacturer="Texas Instruments", Operating Temperature Range(C)="-40 to 85", Rating=Automotive, tpd @ Nom Voltage(Max)(ns)=9,5.1,4.7,3.8, Voltage(Nom)(V)=1.8,2.5,3.3,5
U7: library part CMP-0093537-1, "FLASH - NOR Memory IC 128Mb (16M x 8) SPI - Quad I/O 133 MHz 8-WSON (6x8)", Digikey Part Number=448-S25FL128SAGNFV003CT-ND, Frequency_Fixed=133MHz, Manufacturer="Cypress Semiconductor", Max Supply Voltage=3.6V, Min Supply Voltage=1.65V, Mouser Part Number=727-25FL128SAGNFV003, Nominal Supply Current=16-100mA, Operating Temperature Range="-40°C to +105°C"
U8: library part CMP-0081409-1, "Automotive Low-Quiescent-Current 1% Accurate Supervisor With Programmable Delay, DSE0006A (WSON-6)", Alternate Manufacturer="Texas Instruments", Operating Temprature Range="-40 to 125 C", Rating=Automotive
U9: library part CMP-0034937-2, "Dimmable Quasi-Resonant LED Lighting Controller, 9 to 21.5 V, -40 to 140 degC, 16-pin SOP (PW16), Green (RoHS & no Sb/Br)", Manufacturer="Texas Instruments", Rating=Automotive, Switching Frequency(Typ)(kHz)=1600
U10: library part CMP-0051598-1, "Automotive Catalog Single 2-Input Positive-OR Gate, DBV0005A, LARGE T&R", F @ Nom Voltage(Max)(Mhz)=75, Generic Part Number=SN74AHC1G32-Q1, ICC @ Nom Voltage(Max)(mA)=0.01, Manufacturer="Texas Instruments", Operating Temperature Range(C)="-40 to 105", Rating=Automotive, tpd @ Nom Voltage(Max)(ns)=11.4,7.5, Voltage(Nom)(V)=3.3,5
U11: library part CMP-0750051-1, "Overvoltage and Undervoltage Reset IC With Time Delay and Manual Reset, DSE0006A (WSON-6)", Alternate Manufacturer="Texas Instruments"
U12: library part CMP-0093674-1, "Sitara™ Microcontrollers", Frequency_Fixed=400MHz, Manufacturer="Texas Instruments", Max Supply Voltage=3.465V, Min Supply Voltage=1.14V, Nominal Supply Current=200-2500mA, Operating Temperature Range="-40°C to +105°C", Part Number=AM2632CPDFHMZCZRQ1
U13 U16: library part CMP-0065229-3, "Asynchronous Communication Between Data Buses, RHL0024A (VQFN-24)", Alternate Manufacturer="Texas Instruments", Alternate PartNumber=SN74AXC8T245RHLT
U14: library part CMP-0051688-3, "Automotive Catalog Single Inverter Gate, DBV0005A (SOT-23-5)", F @ Nom Voltage(Max)(Mhz)=75, Generic Part Number=SN74AHC1G04-Q1, ICC @ Nom Voltage(Max)(mA)=0.01, Manufacturer="Texas Instruments", Operating Temperature Range="-40 to 125 C", Rating=Automotive, tpd @ Nom Voltage(Max)(ns)=10.6,7.5, Voltage(Nom)(V)=3.3,5
U15: library part CMP-0088841-1, "e.MMC Memory, 8GB NOR FLASH memory", Digikey Part Number=MTFC8GAMALNA-AATTR-ND, Frequency_Fixed=200MHz, Manufacturer=Micron, Max Supply Voltage=3.6V, Min Supply Voltage=1.7V, Mouser Part Number=340-354324-TRAY, Nominal Supply Current=90-150mA, Operating Temperature Range="-40°C to +105°C"
U17: library part CMP-0082079-1, "Automotive Single Schmitt-Trigger Inverter, DCK0005A (SOT-SC70-5)", Alternate Manufacturer="Texas Instruments", Operating Temperature Range="-40 to 125 C", Rating=Automotive
U18: library part CMP-0095233-1, "Four channel unidirectional level shifter 14-WQFN -40 to 125", Digikey Part Number=296-TXU0104BQARCT-ND, Manufacturer="Texas Instruments", Mouser Part Number=595-TXU0104BQAR, Nominal Supply Current=2.5uA, Operating Temperature Range="-40°C to +125°C"
U19: library part CMP-0860382-1, "SN74AXC2T245RSW, RSW0010A (UQFN-10)", Alternate Manufacturer="Texas Instruments"
U20: library part CMP-0860295-1, "Automotive Catalog Single 5-Ohm SP3T Analog Switch 5-V/3.3-V 3:1 Analog Multiplexer/Demultiplexer, DCU0008A (VSSOP-8)", Alternate Manufacturer="Texas Instruments", Operating Temperature Range="-40 to 125 C", Rating=Automotive
U21: library part CMP-0860146-1, "Automotive Grade, Remote and Local Temperature Sensor with N-Factor and Series-R Correction, DGK0008A (VSSOP-8)", Alternate Manufacturer="Texas Instruments", Operating Temperature Range="-40 to 125 C", Rating=Automotive
U22: library part CMP-0861099-1, "Automotive high-input voltage supervisor with manual reset and programmable-reset time delay, DBV0005A (SOT-23-5)", Alternate Manufacturer="Texas Instruments", Operating Temperature Range="-40 to 125 C", Rating=Automotive
U23: library part CMP-0081107-1, "5.5-V, 1.5-A, 100-mohm Load Switch with Output Discharge, DCK0006A (SOT-SC70-6)", Alternate Manufacturer="Texas Instruments", Alternate PartNumber=TPS22919DCKR
Y1: library part CMP-0082061-2, "Oscillator, 25 MHz, 15 pF, SMD", Frequency Stability="10 ppm", Frequency_Fixed=25MHz, Load Capacitance="15 pF", Manufacturer="ECS Inc.", Supplier Part Number 1=XC2211CT-ND
ZZ1: library part CMP-0003616-3
ZZ2: library part CMP-0077236-1
ZZ3: library part CMP-0077237-1
ZZ4 ZZ5: library part CMP-0077238-1

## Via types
v1: diameter 20, hole 10, Top Layer to Bottom Layer, tented top, 596 vias
v2: diameter 16, hole 8, Top Layer to Bottom Layer, tented both sides, 126 vias
v3: diameter 16, hole 8.01, Top Layer to Bottom Layer, tented top, 63 vias
v4: diameter 19.68, hole 7.87, Top Layer to Bottom Layer, 37 vias
v5: diameter 16, hole 8.02, Top Layer to Bottom Layer, tented bottom, 22 vias
v6: diameter 24.8, hole 12.99, Top Layer to Bottom Layer, 6 vias
v7: diameter 19.68, hole 7.87, Top Layer to Bottom Layer, tented both sides, 6 vias

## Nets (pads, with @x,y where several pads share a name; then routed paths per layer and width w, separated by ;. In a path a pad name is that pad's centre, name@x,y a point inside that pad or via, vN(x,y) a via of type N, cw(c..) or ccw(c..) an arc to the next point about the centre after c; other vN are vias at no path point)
1V2_EN: U3.13 U6.3 | length 1527.1
  Top Layer w9.4: U3.13@2645.51,2380.32 2645.51,2366.91 v1(2659.09,2353.32)
  Top Layer w10: v1(1673.59,1576.12) 1687.5,1590.03 U6.3@1715,1590.03
  SIGNAL1 w10: v1(1673.59,1576.12) 1993.91,1896.44 2441.01,1896.44 2590.84,2046.27 2590.84,2285.07 v1(2659.09,2353.32)
1V2_OB: C11.1 J3.1 L3.2 R7.2 U3.7 U3.14 | length 796.8
  Top Layer w9.4: v1(2478.68,2388.45) 2490.24,2400.01 U3.7@2535.27,2400.01 ; U3.14@2645.51,2400.01 2811.09,2400.01 L3.2@2812.21,2398.89 ; v1(2752.64,2253.62) 2755.5,2253.62 2764.04,2262.16 2798.38,2262.16 C11.1@2812.38,2276.16 2812.21,2276.34 2798.38,2290.16 2762.44,2290.16 2755.5,2297.1 v1(2752.64,2297.1)
  Top Layer w11.81: C11.1@2812.21,2276.34 L3.2@2812.21,2398.89 ; C11.1@2812.38,2276.16 R7.2@2812.38,2184.26 2813.37,2184.26 2826.16,2171.46 2826.16,2103.11 2851.54,2077.73 J3.1@2851.54,1984.78
1V2_PG: R10.1 U3.4 U6.1 | length 172.6
  Top Layer w9.4: v1(2539.89,2502.61) 2560.86,2481.64 U3.4@2560.86,2464.97
  Top Layer w10: U6.1@1715,1641.21 v1(1715,1669.08)
  Top Layer w14.5: v1(1667.92,1656.58) 1683.29,1641.21 U6.1@1715,1641.21
  Top Layer w15: R10.1@2656.86,2112.99 v1(2701.86,2112.99)
3V3_EN: U2.13 U10.4 | length 1447.5
  Top Layer w9.4: U2.13@1904.68,2380.32 1904.68,2366.91 v1(1918.26,2353.32)
  Top Layer w10: U10.4@1822.31,1314.67 v1(1864.7,1314.67)
  Bottom Layer w9.4: v1(1864.7,1314.67) 1689,1314.67 1640.21,1363.46 1640.21,1643.4 1612.8,1670.81 1612.8,1777.1 1878.85,2043.15 1878.85,2313.91 v1(1918.26,2353.32)
3V3_OB: C16.1 J5.1 L2.2 R5.2 R9.2 U2.7 U2.14 | length 713.7
  Top Layer w6.5: L2.2@1925.38,2612.48 1925.38,2567.16 L2.2@1945.13,2547.41 ; R5.2@2007.02,2547.41 R5.2@2018.69,2535.74 2089.84,2535.74 R9.2@2095.46,2530.13 ; C16.1@2052.94,2349.07 C16.1@2067.21,2349.07
  Top Layer w9.4: v1(1737.85,2388.45) 1749.41,2400.01 U2.7@1794.44,2400.01
  Top Layer w10: U2.14@1904.68,2400.01 1964.6,2400.01 ; C16.1@2015.54,2349.07 C16.1@2052.94,2349.07 2056.54,2345.47 J5.1@2056.54,1978.66
  other v1: 1999.22,2408.28 1999.22,2442.38 1999.22,2476.48
3V3_PG: R5.1 U2.4 U4.C1 U6.5 | length 1616
  Top Layer w8: v1(3205.72,2227.71) 3207.65,2229.64 3207.65,2240.9 3219.96,2253.21 U4.C1@3219.96,2253.67
  Top Layer w9.4: v1(1799.06,2502.61) 1820.03,2481.64 U2.4@1820.03,2464.97
  Top Layer w14: v1(1870.52,1536.56) U6.5@1870.52,1564.44
  Top Layer w14.5: U6.5@1870.52,1564.44 1902.23,1564.44 v1(1917.6,1549.07) ; v1@1990.7,2665.22 v1(1990.7,2666.71) ; R5.1@2012.19,2615.74 R5.1@2018.69,2615.74 R5.1@2025.19,2615.74 ; v1@2056.31,2665.22 v1(2056.31,2666.71)
  POWER1 w14.5: v1(2056.31,2666.71) 2162.42,2666.71 2192.47,2636.67 2221.15,2636.67 2250.52,2666.03 2910.08,2666.03 2910.76,2666.71 3205.72,2371.75 v1(3205.72,2227.71)
5V: C7.1 C14.1 C26.1 C69.1 C503.1 C506.1 J6.2 J13.1 J15.1 R22.2 R24.2 R28.2 R519.2 TP4.1 U2.10 U2.11 U2.12 U8.3 U8.4 U10.5 U11.2 U11.6 U22.2 | length 780.8
  Top Layer w6.5: J6.2@1611.54,1978.66 1681.37,2048.49 1795.33,2048.49 1878.65,1965.17 C69.1@1878.65,1912.3
  Top Layer w9.4: 1828.26,2311.39 1839.72,2322.85 U2.10@1839.72,2354.73 ; C7.1@1859.4,2297.27 1859.4,2311.58 ; U2.11@1859.4,2354.73 1859.38,2311.58 ; U2.12@1879.09,2354.73 1879.09,2331.27 1859.4,2311.58
  Top Layer w10: 1447.44,1267.34 U11.6@1471.24,1267.34 1471.24,1283.96 1462.34,1292.86 1450.87,1292.86 ; U11.2@1490.93,1220.1 1490.93,1179.45 v1(1493.44,1176.94)
  Top Layer w20: U22.2@1875.94,1858.29 1875.94,1866.16 1878.65,1868.87 C69.1@1878.65,1912.3
  Top Layer w25: 1448.44,1403.87 1448.44,1421.34 ; 1495.69,1403.87 1495.69,1421.34
  Bottom Layer w20: v1(2386.96,375.92) R519.2@2386.96,417.66
  other v1: 3569.94,-155.83 2902.34,-117.15 3569.94,-112.52 2902.34,-73.84 3569.94,-69.21 2902.34,-30.53 1498.08,1137.13 1563.56,1137.13 1627.15,1137.13 1422.17,1341.11 1481.04,1341.11 1421.58,1386.77 1513.76,1386.77 1835.37,1436.79 1835.37,1481.47 1679.58,2154.04 1738.48,2154.04 1787.38,2154.04 1840.3,2154.04 1679.58,2217.29 1738.48,2217.29 1787.38,2217.29 1818.94,2297.9
5V_FB: C2.2 R2.2 R3.1 U1.5
  other v1: 891.61,2393.23 936.4,2393.23 904.05,2640.61 948.85,2640.61 878.18,2707.49 878.18,2752.28
5V_OB: C3.1 C15.1 J6.1 L1.2 R3.2
5V_SW: C1.2 D500.1 L1.1 R1.1 U1.8
  other v1: 1014.03,2801 1088.82,2801 1163.62,2801 570.24,2864.4 635.03,2864.4 1014.03,2875.8 1088.82,2875.8 1163.62,2875.8 540.24,2894.19 605.03,2894.19
B_LED_IADJ_PWM: R50.1 U12.C2 | length 1054.1
  Top Layer w6.5: v2(2503.4,1083.56) 2503.4,1083.45 2518.58,1068.28 U12.C2@2518.58,1068.17 ; v1(3232.14,1447.56) 3234.72,1450.14 3234.72,1460.11 3240.8,1466.2 R50.1@3240.8,1506.89
  SIGNAL2 w6.5: v2(2503.4,1083.56) 2481.68,1105.28 2481.68,1128.62 2498.78,1145.72 2498.78,1193.18 2531.89,1226.29 2544.13,1226.29 2660.22,1342.38 3128.39,1342.38 v1@3236.16,1450.16
BLUE_CATH: D10.2 J2.6 J16.4 Q4.3 Q4.8 | length 704.8
  Top Layer w6.5: Q4.3@4272.35,2231.59 Q4.3@4273.57,2232.81
  Top Layer w15: Q4.3@4273.57,2232.81 Q4.8@4306.38,2232.81 ; Q4.8@4307.78,2236.51 4308.27,2236.02 4308.27,2210.98 4328.36,2190.89 4381.43,2190.89 4412.25,2221.7 ; D10.2@4412.25,2246.3 4412.25,2221.7 ; J16.4@4646.25,2107.62 4526.33,2107.62 4412.25,2221.7
  Bottom Layer w6.5: J2.6@4454.68,2160.94 J2.6@4466.49,2160.94
  Bottom Layer w15: J2.6@4466.49,2160.94 4519.8,2107.62 J16.4@4646.25,2107.62
BLUE_LED_EN: R81.1 U12.M1 | length 3404.6
  Top Layer w6.5: v1(2409.95,784.7) U12.M1@2487.08,784.7 ; v1(4230.97,1971.88) 4230.97,1975.54 4235.92,1980.48 4235.92,1994.15 R81.1@4242.51,2000.74
  SIGNAL2 w6.5: v1(2409.95,784.7) 2337.31,857.34 2337.31,1501.1 2439.26,1603.05 2680.47,1603.05 2725.26,1558.26 3430.97,1558.26 ; 3431.02,1558.21 3430.97,1558.26 ; v1(4230.97,1971.88) 4230.97,1948.2 4240.76,1938.41 4281.46,1938.41 4292.56,1949.51 4292.56,1989.94 4225.84,2056.66 3807.02,2056.66 3634.43,1884.07 3634.43,1606.07 3586.62,1558.26 3430.97,1558.26
BROWNOUT_RST: R77.1 U12.A10 U22.1 | length 1431.5
  Top Layer w6.5: R77.1@1927.49,1911 1925.52,1911 1913.34,1898.82 U22.1@1913.34,1858.29 1913.34,1850.41 2150.55,1613.21 2617.01,1613.21 2783.55,1446.67 2783.55,1240.51 2763.79,1220.75 2763.79,1167.9 2763.79,1139.59 2770.55,1132.83 U12.A10@2770.55,1131.16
